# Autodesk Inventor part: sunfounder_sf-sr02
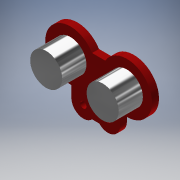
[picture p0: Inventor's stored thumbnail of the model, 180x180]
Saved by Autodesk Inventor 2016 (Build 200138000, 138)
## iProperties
Created: 2016-07
Part Number: sunfounder_sf-sr02
Material: Generic
Document SubType Name: Modeling
Designer: jose
Density: 1 g/cm^3
Appearance: Default
Author: jose
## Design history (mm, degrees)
sketch "Sketch1"
  geometry: L1 (13.915, 33.777)-(20.471, 33.777); L2 (27.8, 15.387)-(27.8, 9.324); L3 (13.944, 5.253)-(17.526, 5.253); L4 (17.193, 33.777)-(17.193, -5.69); L5 (3.67, 14.864)-(3.67, 9.324); L6 (21.856, 9.324)-(-4.944, 9.324); A1 r 12.51 centre (3.174, 27.364) between (13.915, 33.777) and (3.67, 14.864); A2 r 12.51 centre (31.241, 27.414) between (27.8, 15.387) and (20.471, 33.777); A3 r 5.944 centre (21.856, 9.324) between (17.526, 5.253) and (27.8, 9.324); A4 r 5.944 centre (9.613, 9.324) between (3.67, 9.324) and (13.944, 5.253)
  constraints: 12 end point, 8 point on circle, 4 centre point, 3 horizontal, 3 vertical, 2 tangent, 1 midpoint, 1 point on line
  dimensions: "d72" = 25.019 diameter of A1; "d73" = 25.019 diameter of A2; "d74" = 53.086 dimension on A2 A1; "d75" = 6.1468 distance edge to line of A2 L1; "d76" = 15.9512 dimension on A2 L2; "d77" = 28.5242 distance between parallel lines of L1 L3; "d78" = 11.8872 diameter of A3; "d79" = 11.8872 diameter of A4; "d80" = 28.06695 distance of A2.centre A1.centre; "d81" = 24.13 distance between parallel lines of L2 L5; "d82" = 5.53996 distance of L5.start L5.end
extrude "Extrusion2" new body sketch "Sketch1" distance "d65" = 3.4544; taper "d66" = 0 deg
sketch "Sketch3"
  geometry: C1 r 7.963 at (3.174, 27.364); C2 r 7.963 at (31.241, 27.414); A1 r 12.51 centre (3.174, 27.364) between (13.915, 33.777) and (3.67, 14.864) reference; A2 r 12.509 centre (31.241, 27.414) between (27.8, 15.387) and (20.471, 33.777) reference; 1 further point
  constraints: 2 centre point, 2 concentric
  dimensions: "d83" = 15.9258 diameter of C1; "d84" = 15.9258 diameter of C2
extrude "Extrusion4" join sketch "Sketch3" distance "d85" = 12.0396; taper "d86" = 0 deg
sketch "Sketch4"
  geometry: C1 r 1.587 at (9.613, 9.324); C2 r 1.587 at (21.856, 9.324); A1 r 5.944 centre (9.613, 9.324) between (3.67, 9.324) and (13.944, 5.253) reference; A2 r 5.944 centre (21.856, 9.324) between (17.526, 5.253) and (27.8, 9.324) reference; 1 further point
  constraints: 2 centre point, 2 concentric
  dimensions: "d87" = 3.175 diameter of C1; "d88" = 3.175 diameter of C2; "d91" = 12.2428 distance of C2.centre C1.centre (derived)
extrude "Extrusion5" cut sketch "Sketch4" stored distance "d89" = 0; taper "d90" = 0 deg
body "Solid2"
